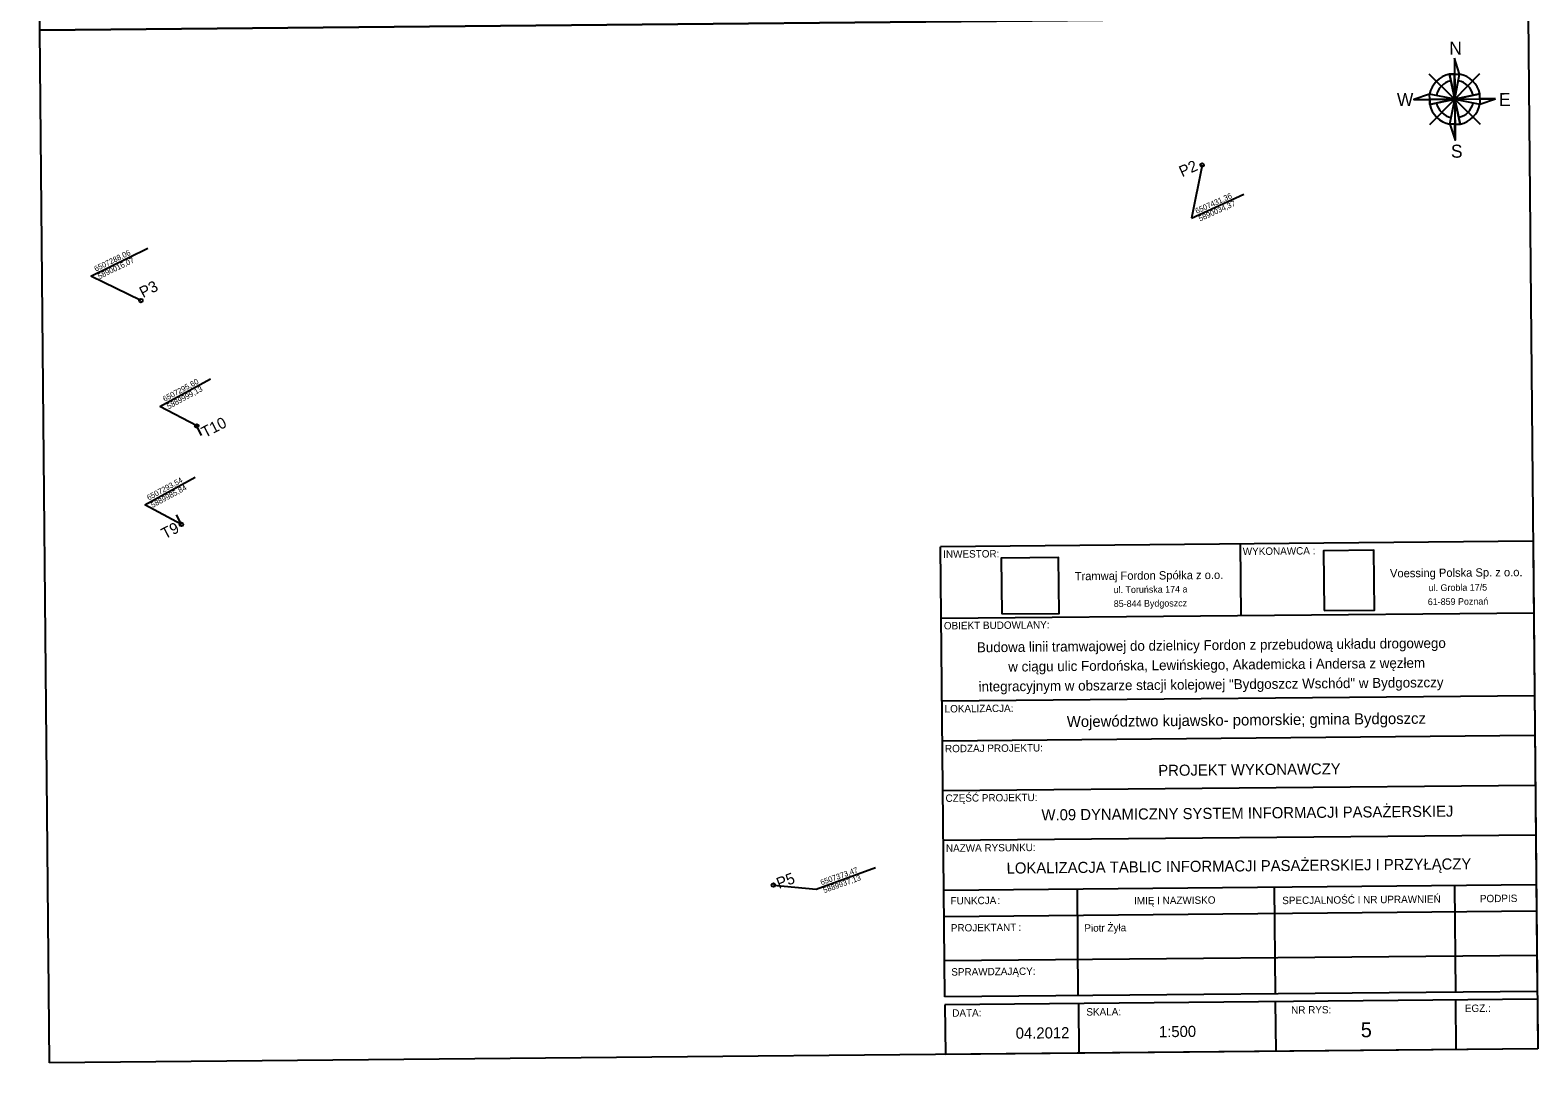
# Model space of a CAD drawing. Extents: x 6505045 to 6511721, y 5887996 to 5893535.
# Drawn here: x 6507273.1 to 6507476.7, y 5889913.1 to 5890052.6 of the extents above; entities that cross this region are included whole.
import ezdxf

# ---------------------------------------------------------------- set-up
doc = ezdxf.new("R2010")
doc.units = 0
for name, color, linetype in [('__legenda', 7, 'Continuous'), ('Default', 7, 'Continuous'), ('P_2 tablice LCD', 7, 'Continuous'), ('P_lokalizacja slupka', 7, 'Continuous'), ('P_opisy', 7, 'Continuous'), ('P_przylacze', 7, 'Continuous'), ('P_tabela', 7, 'Continuous'), ('P_wsporzedne', 7, 'Continuous'), ('P_znak północy', 7, 'Continuous'), ('SA_Linie-020', 7, 'Continuous'), ('SA_Stempel_Text-020', 7, 'Continuous'), ('SA_Stempel_Text-030', 7, 'Continuous'), ('SA_Stempel_Text-035', 7, 'Continuous'), ('SA_Unterschrift_Text', 7, 'Continuous')]:
    doc.layers.add(name, color=color, linetype=linetype)

msp = doc.modelspace()

# ---------------------------------------------------------------- linework, layer by layer
at = {"layer": '__legenda'}
msp.add_lwpolyline([(6507447.84, 5889974.21), (6507454.64, 5889974.28), (6507454.57, 5889982.35), (6507447.77, 5889982.28)], close=True, dxfattribs=at)
at = {"layer": 'Default'}
msp.add_lwpolyline([(6507404.32, 5889973.75), (6507412.05, 5889973.82), (6507411.98, 5889981.35), (6507404.25, 5889981.28)], close=True, dxfattribs=at)
at = {"layer": 'P_2 tablice LCD'}
for p, q in [((6507296.27, 5889997.84), (6507295.6, 5889999.13)), ((6507293.54, 5889985.84), (6507292.86, 5889987.13))]:
    msp.add_line(p, q, dxfattribs=at)
at = {"layer": 'P_lokalizacja slupka'}
for centre in [(6507295.6, 5889999.13), (6507295.6, 5889999.13), (6507293.54, 5889985.84)]:
    msp.add_circle(centre, 0.25, dxfattribs=at)
at = {"layer": 'P_przylacze'}
for centre in [(6507431.36, 5890034.37), (6507431.36, 5890034.37), (6507288.06, 5890016.07), (6507288.06, 5890016.07), (6507373.47, 5889937.13), (6507373.47, 5889937.13)]:
    msp.add_circle(centre, 0.25, dxfattribs=at)
at = {"layer": 'P_tabela'}
for p, q in [((6507274.41, 5890052.58), (6507273.11, 5890192.03)), ((6507274.41, 5890052.58), (6507475.4, 5890054.46)), ((6507475.4, 5890054.46), (6507274.41, 5890052.58)), ((6507475.4, 5890054.46), (6507476.7, 5889915.01)), ((6507275.72, 5889913.13), (6507274.41, 5890052.58)), ((6507476.7, 5889915.01), (6507275.72, 5889913.13))]:
    msp.add_line(p, q, dxfattribs=at)
at = {"layer": 'P_wsporzedne'}
for p, q in [((6507431.36, 5890034.37), (6507429.95, 5890027.2)), ((6507431.36, 5890034.37), (6507429.95, 5890027.2)), ((6507429.95, 5890027.2), (6507437.02, 5890030.43)), ((6507429.95, 5890027.2), (6507437.02, 5890030.43)), ((6507281.32, 5890019.36), (6507288.98, 5890023.15)), ((6507281.32, 5890019.36), (6507288.98, 5890023.15)), ((6507288.06, 5890016.07), (6507281.32, 5890019.36)), ((6507288.06, 5890016.07), (6507281.32, 5890019.36)), ((6507290.64, 5890001.75), (6507297.45, 5890005.5)), ((6507290.64, 5890001.75), (6507297.45, 5890005.5)), ((6507295.6, 5889999.13), (6507290.64, 5890001.75)), ((6507295.6, 5889999.13), (6507290.64, 5890001.75)), ((6507288.58, 5889988.47), (6507295.38, 5889992.22)), ((6507293.54, 5889985.84), (6507288.58, 5889988.47)), ((6507379.25, 5889936.59), (6507387.28, 5889939.5)), ((6507379.25, 5889936.59), (6507387.28, 5889939.5)), ((6507373.47, 5889937.13), (6507379.25, 5889936.59)), ((6507373.47, 5889937.13), (6507379.25, 5889936.59))]:
    msp.add_line(p, q, dxfattribs=at)
at = {"layer": 'P_znak północy'}
for p, q in [((6507465.43, 5890048.78), (6507465.53, 5890037.74)), ((6507465.43, 5890048.78), (6507465.53, 5890037.74)), ((6507465.46, 5890043.26), (6507462.03, 5890046.64)), ((6507465.46, 5890043.26), (6507462.03, 5890046.64)), ((6507464.75, 5890046.63), (6507465.45, 5890046.64)), ((6507464.75, 5890046.63), (6507465.45, 5890046.64)), ((6507465.47, 5890043.26), (6507464.75, 5890046.63)), ((6507465.47, 5890043.26), (6507464.75, 5890046.63)), ((6507465.45, 5890046.64), (6507466.14, 5890046.64)), ((6507465.45, 5890046.64), (6507466.14, 5890046.64)), ((6507465.47, 5890043.26), (6507466.14, 5890046.64)), ((6507465.47, 5890043.26), (6507466.14, 5890046.64)), ((6507465.48, 5890043.27), (6507468.86, 5890046.71)), ((6507465.48, 5890043.27), (6507468.86, 5890046.71)), ((6507465.47, 5890043.26), (6507462.09, 5890043.92)), ((6507465.47, 5890043.26), (6507462.09, 5890043.92)), ((6507465.47, 5890043.26), (6507468.85, 5890043.98)), ((6507465.47, 5890043.26), (6507468.85, 5890043.98)), ((6507459.96, 5890043.21), (6507471, 5890043.31)), ((6507459.96, 5890043.21), (6507471, 5890043.31)), ((6507465.48, 5890043.27), (6507462.09, 5890039.81)), ((6507465.48, 5890043.27), (6507462.09, 5890039.81)), ((6507462.1, 5890042.54), (6507465.47, 5890043.26)), ((6507462.1, 5890043.23), (6507465.46, 5890043.26)), ((6507465.46, 5890043.26), (6507462.1, 5890042.54)), ((6507462.1, 5890042.54), (6507465.47, 5890043.26)), ((6507462.1, 5890043.23), (6507465.46, 5890043.26)), ((6507465.46, 5890043.26), (6507462.1, 5890042.54)), ((6507462.1, 5890042.54), (6507462.1, 5890043.23)), ((6507462.1, 5890042.54), (6507462.1, 5890043.23)), ((6507464.82, 5890039.87), (6507465.47, 5890043.26)), ((6507464.82, 5890039.87), (6507465.47, 5890043.26)), ((6507465.47, 5890043.26), (6507468.86, 5890042.6)), ((6507465.47, 5890043.26), (6507466.2, 5890039.89)), ((6507465.47, 5890043.26), (6507468.86, 5890042.6)), ((6507465.47, 5890043.26), (6507466.2, 5890039.89)), ((6507465.48, 5890043.27), (6507468.92, 5890039.88)), ((6507465.48, 5890043.27), (6507468.92, 5890039.88))]:
    msp.add_line(p, q, dxfattribs=at)
for points in [[(6507465.43, 5890048.78), (6507465.45, 5890046.64), (6507465.45, 5890046.64), (6507466.14, 5890046.64), (6507465.43, 5890048.78)], [(6507465.43, 5890048.78), (6507465.45, 5890046.64), (6507465.45, 5890046.64), (6507466.14, 5890046.64), (6507465.43, 5890048.78)], [(6507465.48, 5890043.27), (6507465.45, 5890046.64), (6507464.75, 5890046.63), (6507465.47, 5890043.26), (6507465.48, 5890043.27)], [(6507465.48, 5890043.27), (6507465.45, 5890046.64), (6507464.75, 5890046.63), (6507465.47, 5890043.26), (6507465.48, 5890043.27)], [(6507462.1, 5890043.23), (6507462.09, 5890043.92), (6507459.96, 5890043.21), (6507462.1, 5890043.23)], [(6507462.1, 5890043.23), (6507462.09, 5890043.92), (6507459.96, 5890043.21), (6507462.1, 5890043.23)], [(6507465.48, 5890043.26), (6507465.48, 5890043.26), (6507465.49, 5890043.26), (6507468.86, 5890043.29), (6507468.85, 5890043.98), (6507465.48, 5890043.26)], [(6507465.48, 5890043.26), (6507465.48, 5890043.26), (6507465.49, 5890043.26), (6507468.86, 5890043.29), (6507468.85, 5890043.98), (6507465.48, 5890043.26)], [(6507465.46, 5890043.26), (6507462.1, 5890043.23), (6507462.1, 5890042.54), (6507465.46, 5890043.26)], [(6507465.46, 5890043.26), (6507462.1, 5890043.23), (6507462.1, 5890042.54), (6507465.46, 5890043.26)], [(6507465.51, 5890039.88), (6507466.2, 5890039.89), (6507465.48, 5890043.25), (6507465.51, 5890039.88)], [(6507465.51, 5890039.88), (6507466.2, 5890039.89), (6507465.48, 5890043.25), (6507465.51, 5890039.88)], [(6507471, 5890043.31), (6507468.86, 5890043.29), (6507468.86, 5890042.6), (6507471, 5890043.31)], [(6507471, 5890043.31), (6507468.86, 5890043.29), (6507468.86, 5890042.6), (6507471, 5890043.31)], [(6507465.51, 5890039.88), (6507464.82, 5890039.87), (6507465.53, 5890037.74), (6507465.51, 5890039.88)], [(6507465.51, 5890039.88), (6507464.82, 5890039.87), (6507465.53, 5890037.74), (6507465.51, 5890039.88)]]:
    msp.add_lwpolyline(points, dxfattribs=at)
for centre, radius, start, end in [((6507465.47, 5890043.26), 3.45, 102.0474, 168.9738), ((6507465.47, 5890043.26), 3.45, 102.0474, 168.9738), ((6507465.48, 5890043.27), 2.53, 102.1671, 169.2958), ((6507465.48, 5890043.27), 2.53, 102.1671, 169.2958), ((6507465.48, 5890043.27), 2.53, 11.7816, 78.9353), ((6507465.48, 5890043.27), 2.53, 11.7816, 78.9353), ((6507465.48, 5890043.26), 3.45, 12.0554, 79.0163), ((6507465.48, 5890043.26), 3.45, 12.0554, 79.0163), ((6507465.47, 5890043.26), 3.45, 192.0538, 259.0158), ((6507465.47, 5890043.26), 3.45, 192.0538, 259.0158), ((6507465.48, 5890043.27), 2.53, 192.3917, 259.0318), ((6507465.48, 5890043.27), 2.53, 192.3917, 259.0318), ((6507465.48, 5890043.27), 2.53, 282.0081, 348.6723), ((6507465.48, 5890043.27), 2.53, 282.0081, 348.6723), ((6507465.48, 5890043.26), 3.45, 282.0538, 349.0163), ((6507465.48, 5890043.26), 3.45, 282.0538, 349.0163)]:
    msp.add_arc(centre, radius, start, end, dxfattribs=at)
at = {"layer": 'SA_Linie-020'}
for p, q in [((6507476.06, 5889983.58), (6507396.06, 5889982.83)), ((6507396.5, 5889936.42), (6507396.06, 5889982.83)), ((6507436.51, 5889983.21), (6507436.6, 5889973.55)), ((6507476.06, 5889983.58), (6507476.63, 5889922.79)), ((6507396.15, 5889973.17), (6507476.15, 5889973.92)), ((6507476.25, 5889962.7), (6507396.26, 5889961.95)), ((6507476.31, 5889957.32), (6507396.31, 5889956.57)), ((6507476.37, 5889950.6), (6507396.37, 5889949.86)), ((6507476.37, 5889950.6), (6507396.37, 5889949.86)), ((6507476.43, 5889943.88), (6507396.43, 5889943.14)), ((6507476.49, 5889937.16), (6507396.5, 5889936.42)), ((6507396.63, 5889922.04), (6507396.5, 5889936.42)), ((6507414.65, 5889922.21), (6507414.52, 5889936.58)), ((6507441.09, 5889936.84), (6507441.23, 5889922.46)), ((6507465.43, 5889937.06), (6507465.56, 5889922.69)), ((6507476.53, 5889933.6), (6507396.53, 5889932.86)), ((6507476.58, 5889927.64), (6507396.59, 5889926.9)), ((6507476.63, 5889922.79), (6507396.63, 5889922.04)), ((6507476.64, 5889921.73), (6507396.64, 5889920.98)), ((6507441.24, 5889921.4), (6507441.3, 5889914.68)), ((6507465.57, 5889921.63), (6507465.63, 5889914.91)), ((6507476.64, 5889921.73), (6507476.7, 5889915.01)), ((6507396.64, 5889920.98), (6507396.7, 5889914.26)), ((6507414.66, 5889921.15), (6507414.72, 5889914.43)), ((6507476.7, 5889915.01), (6507396.7, 5889914.26))]:
    msp.add_line(p, q, dxfattribs=at)

# ---------------------------------------------------------------- texts
at = {"layer": 'P_opisy'}
for s, rotation, p in [('P2', 24.4893, (6507428.67, 5890032.71)), ('P2', 24.4893, (6507428.67, 5890032.71)), ('P3', 27.1433, (6507288.35, 5890016.39)), ('P3', 27.1433, (6507288.35, 5890016.39)), ('T10', 27.2775, (6507296.72, 5889997.5)), ('T10', 27.2775, (6507296.72, 5889997.5)), ('T9', 27.2775, (6507291.3, 5889983.81)), ('P5', 20.5225, (6507374.22, 5889936.61))]:
    msp.add_text(s, height=1.501, rotation=rotation, dxfattribs=at).set_placement(p)
at = {"layer": 'P_wsporzedne'}
for s, rotation, p in [('6507431,36', 24.2067, (6507430.64, 5890027.77)), ('6507431,36', 24.2067, (6507430.64, 5890027.77)), ('5890034,37', 24.2067, (6507431.1, 5890026.74)), ('5890034,37', 24.2067, (6507431.1, 5890026.74)), ('6507288,06', 25.9246, (6507281.98, 5890019.96)), ('6507288,06', 25.9246, (6507281.98, 5890019.96)), ('5890016,07', 25.9246, (6507282.47, 5890018.94)), ('5890016,07', 25.9246, (6507282.47, 5890018.94)), ('6507295,60', 28.4773, (6507291.28, 5890002.38)), ('6507295,60', 28.4773, (6507291.28, 5890002.38)), ('5889999,13', 28.4773, (6507291.82, 5890001.38)), ('5889999,13', 28.4773, (6507291.82, 5890001.38)), ('6507293,54', 28.4773, (6507289.12, 5889989.05)), ('5889985,84', 28.4773, (6507289.66, 5889988.05)), ('6507373,47', 19.5219, (6507379.97, 5889937.11)), ('6507373,47', 19.5219, (6507379.97, 5889937.11)), ('5889937,13', 19.5219, (6507380.35, 5889936.05)), ('5889937,13', 19.5219, (6507380.35, 5889936.05))]:
    msp.add_text(s, height=0.751, rotation=rotation, dxfattribs=at).set_placement(p)
at = {"layer": 'P_znak północy'}
for s, p in [('N', (6507464.75, 5890049.26)), ('N', (6507464.75, 5890049.26)), ('W', (6507457.68, 5890042.33)), ('W', (6507457.68, 5890042.33)), ('E', (6507471.46, 5890042.32)), ('E', (6507471.46, 5890042.32)), ('S', (6507464.97, 5890035.35)), ('S', (6507464.97, 5890035.35))]:
    msp.add_text(s, height=1.76, rotation=0.535, dxfattribs=at).set_placement(p)
at = {"layer": 'SA_Stempel_Text-020'}
for s, p in [('INWESTOR:', (6507396.41, 5889981.32)), ('WYKONAWCA :', (6507436.86, 5889981.7)), ('OBIEKT BUDOWLANY:', (6507396.5, 5889971.66)), ('LOKALIZACJA:', (6507396.6, 5889960.44)), ('RODZAJ PROJEKTU:', (6507396.65, 5889955.06)), ('CZĘŚĆ PROJEKTU:', (6507396.72, 5889948.37)), ('NAZWA RYSUNKU:', (6507396.78, 5889941.62)), ('FUNKCJA', (6507397.41, 5889934.52)), ('IMIĘ I NAZWISKO', (6507422.18, 5889934.52)), ('SPECJALNOŚĆ I NR UPRAWNIEŃ', (6507442.19, 5889934.56)), ('PODPIS', (6507468.88, 5889934.81)), (':', (6507403.74, 5889934.58)), ('PROJEKTANT', (6507397.44, 5889930.86)), (':', (6507406.58, 5889930.95)), ('SPRAWDZAJĄCY:', (6507397.5, 5889924.91)), ('DATA:', (6507397.63, 5889919.36)), ('SKALA:', (6507415.74, 5889919.51)), ('NR RYS:', (6507443.39, 5889919.77)), ('EGZ.:', (6507466.85, 5889919.99))]:
    msp.add_text(s, height=1, rotation=0.535, dxfattribs=at).set_placement(p)
at = {"layer": 'SA_Stempel_Text-030'}
for s, height, p in [('04.2012', 1.5, (6507406.2, 5889916.39)), ('1:500', 1.5, (6507425.54, 5889916.59)), ('5', 2, (6507452.8, 5889916.58))]:
    msp.add_text(s, height=height, rotation=0.535, dxfattribs=at).set_placement(p)
at = {"layer": 'SA_Stempel_Text-035'}
for s, height, p in [('Budowa linii tramwajowej do dzielnicy Fordon z przebudową układu drogowego', 1.35, (6507400.96, 5889968.57)), ('w ciągu ulic Fordońska, Lewińskiego, Akademicka i Andersa z węzłem', 1.35, (6507405.19, 5889965.96)), ('integracyjnym w obszarze stacji kolejowej "Bydgoszcz Wschód" w Bydgoszczy', 1.35, (6507401.19, 5889963.27)), ('Województwo kujawsko- pomorskie; gmina Bydgoszcz', 1.5, (6507413.1, 5889958.47)), ('PROJEKT WYKONAWCZY', 1.5, (6507425.45, 5889951.87)), ('W.09 DYNAMICZNY SYSTEM INFORMACJI PASAŻERSKIEJ', 1.5, (6507409.68, 5889945.86)), ('LOKALIZACJA TABLIC INFORMACJI PASAŻERSKIEJ I PRZYŁĄCZY', 1.5, (6507404.97, 5889938.68))]:
    msp.add_text(s, height=height, rotation=0.535, dxfattribs=at).set_placement(p)
at = {"layer": 'SA_Unterschrift_Text'}
for s, height, p in [('Tramwaj Fordon Spółka z o.o.', 1.125, (6507414.16, 5889978.29)), ('Voessing Polska Sp. z o.o.', 1.125, (6507456.74, 5889978.68)), ('ul. Toruńska 174 a', 0.9, (6507419.42, 5889976.56)), ('ul. Grobla 17/5', 0.9, (6507461.96, 5889976.83)), ('85-844 Bydgoszcz', 0.9, (6507419.44, 5889974.68)), ('61-859 Poznań', 0.9, (6507461.84, 5889974.94)), ('Piotr Żyła', 1, (6507415.47, 5889930.84))]:
    msp.add_text(s, height=height, rotation=0.535, dxfattribs=at).set_placement(p)

doc.saveas('drawing.dxf')
